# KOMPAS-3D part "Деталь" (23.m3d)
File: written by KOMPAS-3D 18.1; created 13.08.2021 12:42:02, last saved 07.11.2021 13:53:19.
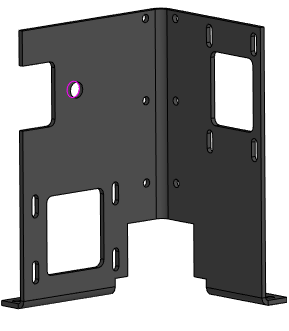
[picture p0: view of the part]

Document properties: Автор: 111; Полное имя файла: C:\Users\admin\Desktop\ffb\23.m3d

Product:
- Part/product: Деталь
    Масса: 0.647503

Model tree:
1. Эскиз:5
2. Листовое тело:2
     Расстояние 1 = 164; Толщина листового тела = 3
3. Сгиб(1) - Листовое тело:2
     Радиус сгиба = 5; Коэффициент = 0.4; Величина сгиба = 10
4. Эскиз:9
5. Элемент выдавливания:4
     Расстояние 2 = 3
6. Элемент выдавливания:5
     Расстояние 2 = -3
7. Элемент выдавливания:6
     Расстояние 2 = -3
8. Эскиз:11
9. Элемент выдавливания:8
     Расстояние 2 = 3
10. Эскиз:12  (with: Листовое тело:2)
11. Элемент выдавливания:9
     Расстояние 2 = 15
12. Элемент выдавливания:10
     Расстояние 2 = 31
13. Сгиб:1  (with: Листовое тело:2)
14. Сгиб(1) - Сгиб:1
     Радиус сгиба = 2; Коэффициент = 0.4; Величина сгиба = 10; Толщина листового тела = 3; Ширина освобождения сгиба = 3; Ширина сгиба = 50; Отступ 1 = 11; Длина 1 = 20; Длина 2 = 10
15. Сгиб:2  (with: Листовое тело:2)
16. Сгиб(1) - Сгиб:2
     Радиус сгиба = 2; Коэффициент = 0.4; Величина сгиба = 10; Радиус сгиба = 2; Толщина листового тела = 3; Ширина освобождения сгиба = 3; Ширина сгиба = 73; Длина 1 = 20; Отступ 2 = 10; Длина 2 = 10
17. Эскиз:13  (with: Сгиб:2, Сгиб:1)
18. Элемент выдавливания:11
     Расстояние 2 = 3
19. Эскиз:15
20. Элемент выдавливания:12
     Расстояние 2 = 3
21. Эскиз:16
22. Элемент выдавливания:13
     Расстояние 2 = 3
23. Эскиз:17
24. Элемент выдавливания:14
     Расстояние 2 = 3
25. Эскиз:20  (with: Листовое тело:2, Элемент выдавливания:8)
26. Эскиз:21  (with: Листовое тело:2)
27. Элемент выдавливания:16
     Расстояние 2 = 3
28. Эскиз:22  (with: Листовое тело:2, Элемент выдавливания:9)
29. Элемент выдавливания:17
     Расстояние 2 = 3
30. Эскиз:24  (with: Листовое тело:2, Сгиб:2)
31. Элемент выдавливания:18
     Расстояние 2 = 3
32. Эскиз:26  (with: Сгиб:1)
33. Элемент выдавливания:19
     Расстояние 2 = -3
